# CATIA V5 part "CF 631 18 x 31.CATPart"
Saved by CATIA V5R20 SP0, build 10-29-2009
Part number: CF 631 18 x 31
Definition: NONE
Nomenclature: CF 631 18 x 31
Source: Unknown
Description: CF 631 18 x 31
Bounding box of the stored display mesh (mm): x -13 to 18, y -17 to 17, z -17 to 17
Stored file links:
  C:\Users\Utente\Desktop\IO LAVORO\3D X SITO CF\X SITO\CF 631\CF 631 18 x 31.CATPart
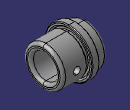
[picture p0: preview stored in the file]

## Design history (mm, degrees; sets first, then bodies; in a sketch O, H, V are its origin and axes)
Body1 "CF 631 18 x 31" (main body)
  Solid1: solid without history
